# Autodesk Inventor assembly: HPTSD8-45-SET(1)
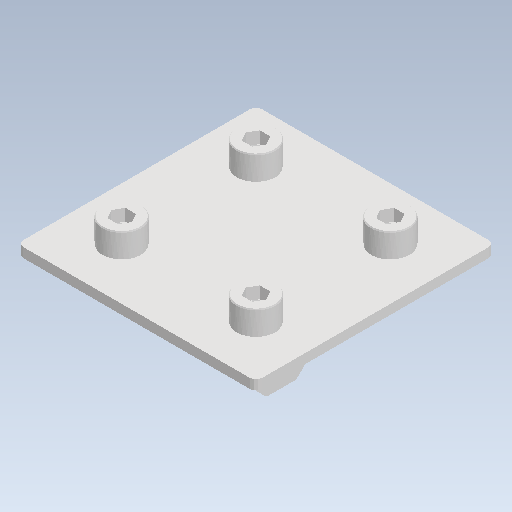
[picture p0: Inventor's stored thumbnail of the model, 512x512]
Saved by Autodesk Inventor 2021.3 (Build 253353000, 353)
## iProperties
Created: 2022-02
Part Number: HPTSD8-45-SET(1)
Document SubType Name: Assembly
Designer: kengo
Author: kengo
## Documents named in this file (4)
- C:\Users\kengo\Documents\S2S_frame\SDC345\frame_misumi_ver12\HPTSD8-45-SET(1).iam
- C:\Users\kengo\Documents\S2S_frame\SDC345\frame_misumi_ver12\HPTSD8-45.ipt
- C:\Users\kengo\Documents\S2S_frame\SDC345\frame_misumi_ver12\HNTT8-8.ipt
- C:\Users\kengo\Documents\S2S_frame\SDC345\frame_misumi_ver12\CBM8-15.ipt
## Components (9 placed, 3 different names)
1. HPTSD8-45
2. HNTT8-8
3. CBM8-15
4. HNTT8-8:1
5. CBM8-15:1
6. HNTT8-8:2
7. CBM8-15:2
8. HNTT8-8:3
9. CBM8-15:3
